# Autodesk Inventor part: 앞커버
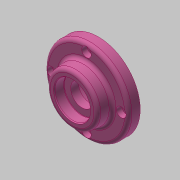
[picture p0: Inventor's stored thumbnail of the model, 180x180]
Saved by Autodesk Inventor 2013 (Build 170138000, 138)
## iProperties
Created: 2017-08
Part Number: 앞커버
Material: 알루미늄 6061
Document SubType Name: Modeling
Designer: mduedu
Density: 2.71 g/cm^3
Mass: 117.256 g
Surface Area: 148.119 cm^2
Volume: 43.2677 cm^3
Author: mduedu
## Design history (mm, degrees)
sketch "스케치1"
  geometry: C1 r 35 at (0, 0); 1 further point
  constraints: 1 centre point, 1 coincident
  dimensions: "d0" = 70 diameter of C1
extrude "돌출1" new body sketch "스케치1" distance "d1" = 10; taper "d2" = 0 deg
sketch "스케치2"
  geometry: C1 r 22 at (0, 0); 1 further point
  constraints: 1 centre point, 1 coincident
  dimensions: "d3" = 44 diameter of C1
node "작업 평면1"
sketch "스케치3"
  geometry: C1 r 21 at (0, 0); 1 further point
  constraints: 1 centre point, 1 coincident
  dimensions: "d5" = 42 diameter of C1
feature "로프트1" sketch "스케치3" dims "d6" = 0, "d7" = 90 deg, "d8" = 0, "d9" = 90 deg
sketch "스케치4"
  geometry: C1 r 24 at (0, 0); 1 further point
  constraints: 1 centre point, 1 coincident
  dimensions: "d86" = 48 diameter of C1
extrude "돌출2" join sketch "스케치4" distance "d10" = 8; taper "d11" = 0 deg
hole "구멍1" diameter "d14" = 40; stored, may be unused: countersink angle "d18" = 90 deg, drill point angle "d20" = 0 deg; dims "d15" = 6, "d16" = 4, "d17" = 2, "d19" = 12, "d87" = 10, "d88" = 10
hole "구멍2" diameter "d23" = 34; stored, may be unused: countersink angle "d27" = 90 deg, drill point angle "d29" = 0 deg; dims "d21" = 10, "d22" = 10, "d24" = 6, "d25" = 4, "d26" = 2, "d28" = 3
hole "구멍3" diameter "d32" = 19; stored, may be unused: countersink angle "d36" = 90 deg, drill point angle "d38" = 0 deg; dims "d30" = 10, "d31" = 10, "d33" = 6, "d34" = 4, "d35" = 2, "d37" = 3
chamfer "모따기1" distance "d39" = 1; stored, may be unused: second distance "d40" = 2, angle "d41" = 45 deg
sketch "스케치5"
  geometry: C1 r 15 at (0, 0); 1 further point
  constraints: 1 centre point, 1 coincident
  dimensions: "d42" = 30 diameter of C1
extrude "돌출3" cut sketch "스케치5" distance "d43" = 8.3; taper "d44" = 0 deg
chamfer "모따기2" distance "d47" = 0.8; stored, may be unused: second distance "d48" = 2, angle "d49" = 30 deg
fillet "모깎기1" dims "d50" = 0.3
fillet "모깎기2" dims "d51" = 0.3
fillet "모깎기3" dims "d52" = 3
sketch "스케치6" dims "d53" = 58
  geometry: 6 further points
  constraints: 2 vertical alignment, 1 coincident, 7 other
  dimensions: "d56" = 360 deg dimension on point (0, 0) point (0, 29) (derived)
sketch "스케치9" dims "d85" = 58 (derived)
  geometry: 6 further points
  constraints: 1 coincident, 1 vertical alignment, 6 other
hole "구멍6" sketch "스케치9" at (-29, 0), (0, -29), (29, 0), (0, 29) diameter "d72" = 4.5; stored, may be unused: countersink angle "d76" = 90 deg, drill point angle "d78" = 0 deg; dims "d73" = 6, "d74" = 8, "d75" = 4.6, "d77" = 8
fillet "모깎기4" dims "d79" = 3
fillet "모깎기5" dims "d80" = 3
fillet "모깎기6" dims "d81" = 3
node "솔리드1"
other parameters: "d4" = 12
